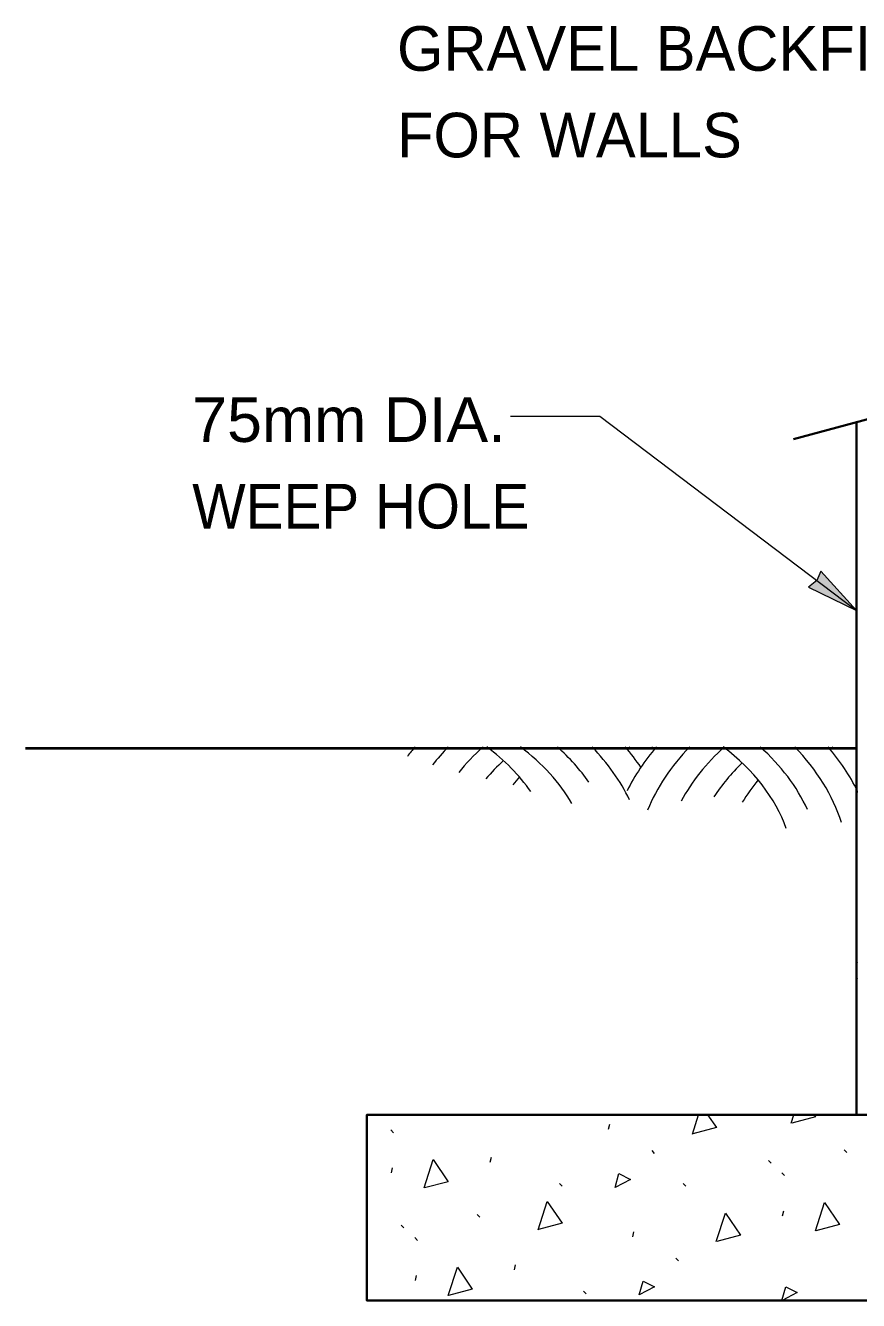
# Model space of a CAD drawing. Extents: x 17672 to 18472, y -9785 to -9267.
# Drawn here: x 18068.7 to 18134.6, y -9679.5 to -9578.7 of the extents above; entities that cross this region are included whole.
import ezdxf

# ---------------------------------------------------------------- set-up
doc = ezdxf.new("R2010")
doc.units = 0
doc.header["$LTSCALE"] = 1.4
for name, color, linetype, lineweight in [('1', 7, 'Continuous', 13), ('15', 7, 'Continuous', 13), ('16', 7, 'Continuous', 13), ('20', 7, 'Continuous', 25)]:
    doc.layers.add(name, color=color, linetype=linetype, lineweight=lineweight)
doc.layers.add('19', color=7, linetype='Continuous')

msp = doc.modelspace()

# ---------------------------------------------------------------- hatches: boundary and pattern name
at = {"layer": '16'}
msp.add_hatch(color=256, dxfattribs=at).paths.add_polyline_path([(18134.457, -9624.944), (18131.631, -9621.822), (18131.307, -9622.557), (18130.663, -9623.099)])

# ---------------------------------------------------------------- linework, layer by layer
at = {"layer": '1', "lineweight": 35}
for p, q in [((18129.469, -9611.395), (18140.709, -9608.341)), ((18134.457, -9664.802), (18134.457, -9610.04)), ((18134.457, -9635.844), (18068.922, -9635.844))]:
    msp.add_line(p, q, dxfattribs=at)
at = {"layer": '1', "lineweight": 40}
msp.add_line((18134.457, -9635.844), (18068.736, -9635.844), dxfattribs=at)
at = {"layer": '1', "lineweight": 25}
for p, q in [((18134.457, -9635.844), (18068.922, -9635.844)), ((18134.423, -9637.4), (18134.457, -9637.461)), ((18134.506, -9639.335), (18134.481, -9639.095))]:
    msp.add_line(p, q, dxfattribs=at)
at = {"layer": '1'}
for p, q in [((18134.491, -9651.947), (18134.499, -9651.932)), ((18134.491, -9652.787), (18134.494, -9652.802)), ((18134.491, -9653.187), (18134.499, -9653.172)), ((18134.491, -9654.028), (18134.494, -9654.042)), ((18134.491, -9654.427), (18134.499, -9654.413)), ((18121.469, -9666.356), (18121.964, -9664.822)), ((18129.283, -9665.498), (18129.501, -9664.822)), ((18097.628, -9666.033), (18097.839, -9666.248)), ((18114.841, -9665.979), (18114.944, -9665.582)), ((18105.488, -9668.574), (18105.579, -9668.194)), ((18118.261, -9667.663), (18118.457, -9667.881)), ((18133.486, -9667.596), (18133.697, -9667.812)), ((18097.675, -9669.432), (18097.763, -9669.038)), ((18127.481, -9668.435), (18127.697, -9668.665)), ((18128.557, -9669.427), (18128.768, -9669.643)), ((18110.959, -9670.261), (18111.17, -9670.474)), ((18120.739, -9670.27), (18120.952, -9670.486)), ((18104.452, -9672.717), (18104.662, -9672.932)), ((18128.604, -9672.827), (18128.692, -9672.432)), ((18098.449, -9673.555), (18098.662, -9673.785)), ((18116.751, -9674.491), (18116.839, -9674.096)), ((18099.523, -9674.547), (18099.734, -9674.763)), ((18120.158, -9676.177), (18120.366, -9676.378)), ((18107.4, -9677.087), (18107.488, -9676.692)), ((18099.569, -9677.947), (18099.658, -9677.552)), ((18112.854, -9678.775), (18113.065, -9678.989))]:
    msp.add_line(p, q, dxfattribs=at)
at = {"layer": '1', "lineweight": 35}
msp.add_lwpolyline([(18134.457, -9664.822), (18095.729, -9664.822), (18095.729, -9679.521), (18187.59, -9679.521), (18187.59, -9664.822), (18158.903, -9664.822)], close=True, dxfattribs=at)
at = {"layer": '1'}
for points in [[(18122.672, -9664.822), (18123.366, -9665.849), (18121.516, -9666.349)], [(18131.074, -9664.822), (18131.199, -9665.003), (18129.329, -9665.491)], [(18158.903, -9664.822), (18134.457, -9664.822), (18134.457, -9664.802)], [(18100.248, -9670.619), (18100.974, -9668.376), (18102.165, -9670.123), (18100.295, -9670.611)], [(18109.27, -9673.918), (18109.993, -9671.677), (18111.167, -9673.41), (18109.314, -9673.91)], [(18131.195, -9674.011), (18131.918, -9671.768), (18133.092, -9673.503), (18131.224, -9674.006)], [(18123.361, -9674.854), (18124.087, -9672.614), (18125.278, -9674.359), (18123.408, -9674.846)], [(18102.16, -9679.131), (18102.886, -9676.888), (18104.057, -9678.621), (18102.189, -9679.126)], [(18128.555, -9679.521), (18128.851, -9678.43), (18129.766, -9678.883), (18128.56, -9679.521)]]:
    msp.add_lwpolyline(points, dxfattribs=at)
for points in [[(18115.366, -9670.572), (18115.663, -9669.476), (18116.582, -9669.947)], [(18117.261, -9679.07), (18117.574, -9677.989), (18118.474, -9678.445)]]:
    msp.add_lwpolyline(points, close=True, dxfattribs=at)
for centre, major_axis, start_param, end_param in [((18122.3, -9645.734), (-26.675, 0), 5.7344252, 5.7796809), ((18122.3, -9645.734), (-24.471, 0), 5.6783592, 5.7742332), ((18122.3, -9645.734), (-22.266, 0), 5.6081662, 5.761688), ((18090.759, -9645.734), (20.062, 0), 0.4649367, 0.7655158), ((18093.41, -9645.734), (20.062, 0), 0.3930143, 0.7655158), ((18093.41, -9645.734), (22.266, 0), 0.4669224, 0.6750191), ((18093.41, -9645.734), (24.471, 0), 0.3369039, 0.6048262), ((18093.41, -9645.734), (26.675, 0), 0.4531045, 0.5487601), ((18141.387, -9645.734), (-26.675, 0), 5.7344252, 5.9359014), ((18095.429, -9621.982), (28.469, 0), 5.5360053, 5.5474825), ((18141.387, -9645.734), (-24.471, 0), 5.6783592, 5.9947455), ((18139.369, -9621.982), (-28.469, 0), 0.7357028, 0.74718), ((18141.387, -9645.734), (-22.266, 0), 5.6081662, 5.9189575), ((18109.445, -9645.734), (20.062, 0), 0.2476684, 0.7655158), ((18109.445, -9645.734), (22.266, 0), 0.321019, 0.6750191), ((18109.445, -9645.734), (24.471, 0), 0.230357, 0.6048262), ((18109.445, -9645.734), (26.675, 0), 0.3466408, 0.5487601), ((18111.463, -9621.982), (28.469, 0), 5.5360053, 5.5474825), ((18122.3, -9645.734), (-20.062, 0), 5.6168531, 5.7376933), ((18141.387, -9645.734), (-20.062, 0), 5.6332046, 5.8501484), ((18124.765, -9645.803), (-20.062, 0), 5.7208514, 5.7710521), ((18143.852, -9645.803), (-20.062, 0), 5.7400219, 5.8777396)]:
    msp.add_ellipse(centre, major_axis=major_axis, ratio=0.719298, start_param=start_param, end_param=end_param, dxfattribs=at)
at = {"layer": '15'}
msp.add_lwpolyline([(18107.091, -9609.567), (18114.163, -9609.567), (18134.457, -9624.944)], dxfattribs=at)
at = {"layer": '16'}
msp.add_lwpolyline([(18134.457, -9624.944), (18131.631, -9621.822), (18131.307, -9622.557), (18130.663, -9623.099)], close=True, dxfattribs=at)

# ---------------------------------------------------------------- texts
at = {"layer": '19'}
for s, width, p in [('75mm DIA.', 1.05, (18081.92, -9611.606)), ('WEEP HOLE', 0.95, (18081.92, -9618.456))]:
    msp.add_text(s, height=3.529, dxfattribs=dict(at, width=width)).set_placement(p)
at = {"layer": '20'}
for s, p in [('GRAVEL BACKFILL', (18098.116, -9582.245)), ('FOR WALLS', (18098.116, -9589.096))]:
    msp.add_text(s, height=3.529, dxfattribs=at).set_placement(p)

doc.saveas('drawing.dxf')
